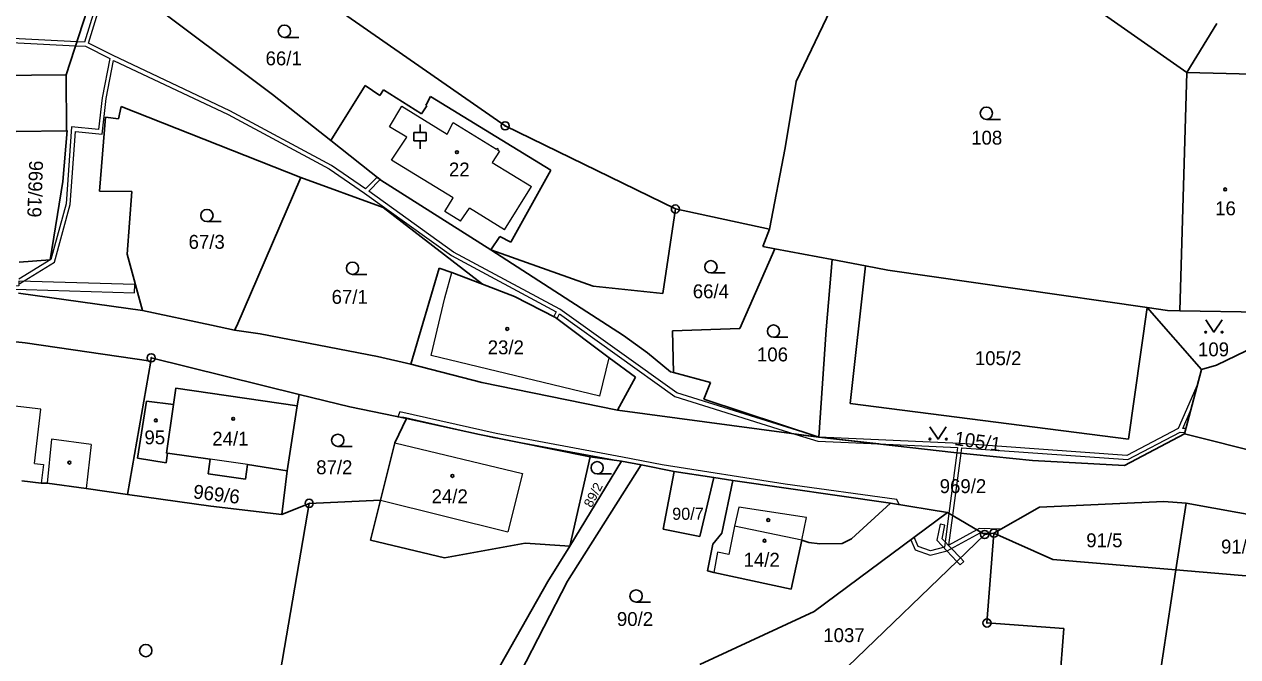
# Model space of a CAD drawing. Extents: x -754970 to -752637, y -970569 to -968179.
# Drawn here: x -753121.7 to -752973.4, y -969459.8 to -969382.5 of the extents above; entities that cross this region are included whole.
import ezdxf
from ezdxf.enums import TextEntityAlignment as Align

# ---------------------------------------------------------------- set-up
doc = ezdxf.new("R2010")
doc.units = 0
doc.header["$LTSCALE"] = 0.68
for name, color, linetype, lineweight in [('1', 7, 'Continuous', 25), ('13', 7, 'Continuous', 13), ('3', 7, 'Continuous', 25), ('4', 7, 'Continuous', 13), ('5', 7, 'Continuous', 25), ('8', 7, 'Continuous', 25)]:
    doc.layers.add(name, color=color, linetype=linetype, lineweight=lineweight)
doc.layers.add('2', color=7, linetype='Continuous')

msp = doc.modelspace()

# ---------------------------------------------------------------- linework, layer by layer
at = {"layer": '1'}
for p, q in [((-753014.52, -969363.86), (-752979.63, -969388.38)), ((-753112.53, -969376.1), (-753116.59, -969388.67)), ((-753091.37, -969391.06), (-753107.35, -969379.07)), ((-753062.94, -969394.9), (-753083.63, -969380.5)), ((-753027.39, -969389.48), (-753022.73, -969379.76)), ((-752975.98, -969382.36), (-752979.63, -969388.38)), ((-752979.63, -969388.38), (-752980.48, -969417.53)), ((-752979.63, -969388.38), (-752969.62, -969388.61)), ((-753125.25, -969388.72), (-753116.59, -969388.67)), ((-753116.56, -969395.51), (-753116.59, -969388.67)), ((-753080.04, -969389.98), (-753084.24, -969396.7)), ((-753080.04, -969389.98), (-753078.27, -969391.19)), ((-753028.7, -969397.57), (-753027.39, -969389.48)), ((-753084.24, -969396.7), (-753091.37, -969391.06)), ((-753077.82, -969390.49), (-753078.27, -969391.19)), ((-753073.17, -969393.44), (-753077.82, -969390.49)), ((-753072.07, -969391.32), (-753072.55, -969392.23)), ((-753072.07, -969391.32), (-753057.36, -969400.33)), ((-753109.88, -969392.51), (-753110.18, -969394.03)), ((-753087.91, -969401.22), (-753109.88, -969392.51)), ((-753072.53, -969392.44), (-753073.17, -969393.44)), ((-753072.55, -969392.23), (-753072.65, -969392.37)), ((-753072.65, -969392.37), (-753072.53, -969392.44)), ((-753111.78, -969393.82), (-753112.5, -969402.88)), ((-753110.18, -969394.03), (-753111.78, -969393.82)), ((-753122.72, -969395.58), (-753116.56, -969395.51)), ((-753116.99, -969401.72), (-753116.45, -969395.48)), ((-753116.56, -969395.51), (-753116.45, -969395.48)), ((-753042.13, -969405.06), (-753062.94, -969394.9)), ((-753078.12, -969401.54), (-753084.24, -969396.7)), ((-753030.65, -969407.55), (-753028.7, -969397.57)), ((-753057.36, -969400.33), (-753062.23, -969409.14)), ((-753118.56, -969411.3), (-753116.99, -969401.72)), ((-753087.91, -969401.22), (-753095.74, -969419.37)), ((-753087.91, -969401.22), (-753077.86, -969404.87)), ((-753064.69, -969410.06), (-753078.12, -969401.54)), ((-753112.5, -969402.88), (-753108.56, -969402.93)), ((-753108.56, -969402.93), (-753109.13, -969410.6)), ((-753077.86, -969404.87), (-753065.7, -969414.26)), ((-753043.66, -969415.4), (-753042.13, -969405.06)), ((-753030.65, -969407.55), (-753042.13, -969405.06)), ((-753031.44, -969409.65), (-753030.65, -969407.55)), ((-753063.6, -969408.43), (-753064.69, -969410.06)), ((-753062.23, -969409.14), (-753063.6, -969408.43)), ((-753109.13, -969410.6), (-753107.27, -969417.5)), ((-753064.69, -969410.06), (-753048.46, -969420.54)), ((-753064.69, -969410.06), (-753052.19, -969414.49)), ((-753029.99, -969409.93), (-753034.24, -969419.67)), ((-753029.99, -969409.93), (-753031.44, -969409.65)), ((-753022.98, -969411.26), (-753029.99, -969409.93)), ((-753118.56, -969411.3), (-753122.34, -969411.56)), ((-753071.02, -969412.3), (-753074.46, -969424.04)), ((-753069.44, -969412.82), (-753071.02, -969412.3)), ((-753023.69, -969419.83), (-753022.98, -969411.26)), ((-753022.98, -969411.26), (-753018.9, -969412.03)), ((-753018.9, -969412.03), (-753020.77, -969428.86)), ((-753018.9, -969412.03), (-753016.16, -969412.55)), ((-753065.7, -969414.26), (-753069.44, -969412.82)), ((-753016.16, -969412.55), (-752984.46, -969417.12)), ((-753065.7, -969414.26), (-753061.79, -969415.76)), ((-753052.19, -969414.49), (-753043.66, -969415.4)), ((-753107.27, -969417.5), (-753122.41, -969415.37)), ((-753056.77, -969418.32), (-753061.79, -969415.76)), ((-752975.99, -969424.16), (-752959, -969415.96)), ((-753107.27, -969417.5), (-753098.82, -969419.27)), ((-752986.78, -969433.23), (-752984.46, -969417.12)), ((-752984.46, -969417.12), (-752977.83, -969424.68)), ((-752984.46, -969417.12), (-752982, -969417.47)), ((-752982, -969417.47), (-752980.48, -969417.53)), ((-752980.48, -969417.53), (-752970.51, -969417.7)), ((-753098.82, -969419.27), (-753096.01, -969419.89)), ((-753095.74, -969419.37), (-753096.01, -969419.89)), ((-753050.24, -969423.29), (-753056.77, -969418.32)), ((-753042.5, -969419.97), (-753034.24, -969419.67)), ((-753121.61, -969421.42), (-753127.82, -969420.82)), ((-753092.88, -969420.35), (-753096.01, -969419.89)), ((-753078.54, -969423.09), (-753092.88, -969420.35)), ((-753048.46, -969420.54), (-753045.56, -969422.64)), ((-753042.36, -969425.08), (-753042.5, -969419.97)), ((-753024.62, -969432.98), (-753023.69, -969419.83)), ((-753106.24, -969423.68), (-753121.61, -969421.42)), ((-753045.56, -969422.64), (-753042.75, -969424.98)), ((-753109.09, -969439.97), (-753106.24, -969423.68)), ((-753106.2, -969423.27), (-753106.24, -969423.68)), ((-753106.2, -969423.27), (-753088.13, -969427.74)), ((-753074.46, -969424.04), (-753078.54, -969423.09)), ((-753074.46, -969424.04), (-753065.79, -969426.3)), ((-753047.03, -969425.62), (-753050.24, -969423.29)), ((-752977.83, -969424.68), (-752975.99, -969424.16)), ((-753047.03, -969425.62), (-753049.22, -969429.69)), ((-753042.75, -969424.98), (-753042.36, -969425.08)), ((-753042.36, -969425.08), (-753037.85, -969426.28)), ((-752979.9, -969432.57), (-752977.83, -969424.68)), ((-753065.79, -969426.3), (-753049.22, -969429.69)), ((-753038.66, -969428.33), (-753037.85, -969426.28)), ((-753107.88, -969435.56), (-753106.79, -969428.57)), ((-753106.79, -969428.57), (-753103.49, -969428.96)), ((-753088.35, -969429.15), (-753088.13, -969427.74)), ((-753088.13, -969427.74), (-753081.93, -969429.27)), ((-753024.62, -969432.98), (-753038.66, -969428.33)), ((-753103.49, -969428.96), (-753104.33, -969434.93)), ((-753088.35, -969429.15), (-753089.6, -969437.1)), ((-753074.99, -969430.69), (-753081.93, -969429.27)), ((-753049.22, -969429.69), (-753024.62, -969432.98)), ((-752986.78, -969433.23), (-753020.77, -969428.86)), ((-753074.99, -969430.69), (-753076.43, -969433.67)), ((-753066.07, -969432.66), (-753074.99, -969430.69)), ((-753066.07, -969432.66), (-753052.54, -969435.38)), ((-753008.12, -969434.83), (-753024.62, -969432.98)), ((-752979.9, -969432.57), (-752987.24, -969436.42)), ((-752965.87, -969436.11), (-752979.9, -969432.57)), ((-753078.17, -969440.69), (-753076.43, -969433.67)), ((-753104.37, -969436.12), (-753107.88, -969435.56)), ((-753104.19, -969434.95), (-753104.37, -969436.12)), ((-753104.33, -969434.93), (-753104.19, -969434.95)), ((-753104.19, -969434.95), (-753098.98, -969435.68)), ((-753098.98, -969435.68), (-753099.23, -969437.46)), ((-753052.54, -969435.38), (-753055.02, -969446.29)), ((-753048.74, -969435.91), (-753055.02, -969446.29)), ((-753052.54, -969435.38), (-753048.74, -969435.91)), ((-753046.31, -969436.35), (-753048.74, -969435.91)), ((-752998.49, -969435.81), (-753008.12, -969434.83)), ((-752987.24, -969436.42), (-752998.49, -969435.81)), ((-753099.23, -969437.46), (-753094.68, -969438.11)), ((-753094.68, -969438.11), (-753094.43, -969436.32)), ((-753089.6, -969437.1), (-753094.43, -969436.32)), ((-753090.24, -969442.45), (-753089.6, -969437.1)), ((-753055.32, -969450.6), (-753046.31, -969436.35)), ((-753046.31, -969436.35), (-753042.27, -969437.18)), ((-753043.63, -969444.23), (-753042.27, -969437.18)), ((-753037.42, -969437.89), (-753042.27, -969437.18)), ((-753122.01, -969438.33), (-753119.63, -969438.61)), ((-753119.63, -969438.61), (-753118.92, -969438.59)), ((-753118.92, -969438.59), (-753114.14, -969439.25)), ((-753037.42, -969437.89), (-753039.14, -969445.14)), ((-753035.13, -969438.29), (-753037.42, -969437.89)), ((-753035.13, -969438.29), (-753036.47, -969444.72)), ((-753015.83, -969441.05), (-753035.13, -969438.29)), ((-753109.09, -969439.97), (-753114.14, -969439.25)), ((-753098.92, -969441.41), (-753109.09, -969439.97)), ((-753090.24, -969442.45), (-753098.92, -969441.41)), ((-753086.89, -969441.07), (-753095.11, -969489.22)), ((-753086.89, -969441.07), (-753090.24, -969442.45)), ((-753078.17, -969440.69), (-753086.89, -969441.07)), ((-753078.17, -969440.69), (-753079.38, -969445.56)), ((-753015.83, -969441.05), (-753020.61, -969445.42)), ((-753008.89, -969442.19), (-753015.83, -969441.05)), ((-753003.21, -969444.72), (-752997.63, -969441.54)), ((-752997.63, -969441.54), (-752982.45, -969440.86)), ((-752982.45, -969440.86), (-752979.72, -969441.05)), ((-752980.96, -969449.2), (-752979.72, -969441.05)), ((-752979.72, -969441.05), (-752957.16, -969445.1)), ((-753008.89, -969442.19), (-753025.16, -969454.29)), ((-753008.89, -969442.19), (-753004.33, -969444.88)), ((-753039.14, -969445.14), (-753043.63, -969444.23)), ((-753036.47, -969444.72), (-753037.56, -969446.06)), ((-753029.33, -969468.96), (-753004.33, -969444.88)), ((-753004.33, -969444.88), (-753003.21, -969444.72)), ((-753003.21, -969444.72), (-753004.06, -969455.7)), ((-753003.21, -969444.72), (-752996, -969447.92)), ((-753079.38, -969445.56), (-753070.36, -969447.75)), ((-753070.36, -969447.75), (-753060.51, -969445.95)), ((-753055.02, -969446.29), (-753060.51, -969445.95)), ((-753057.73, -969450.62), (-753055.02, -969446.29)), ((-753037.56, -969446.06), (-753038.21, -969449.31)), ((-753027.97, -969451.57), (-753026.7, -969445.59)), ((-753025.83, -969445.86), (-753026.7, -969445.59)), ((-753024.49, -969446), (-753025.83, -969445.86)), ((-753021.74, -969445.97), (-753024.49, -969446)), ((-753020.61, -969445.42), (-753021.74, -969445.97)), ((-753038.21, -969449.31), (-753037.45, -969449.51)), ((-752996, -969447.92), (-752980.96, -969449.2)), ((-752988.75, -969500.54), (-752980.96, -969449.2)), ((-752980.96, -969449.2), (-752969.96, -969450.14)), ((-753057.73, -969450.62), (-753079.26, -969488.65)), ((-753061.11, -969461.85), (-753055.32, -969450.6)), ((-753027.97, -969451.57), (-753037.45, -969449.51)), ((-753025.16, -969454.29), (-753039.13, -969460.76)), ((-753004.06, -969455.7), (-752994.68, -969456.37)), ((-752994.68, -969456.37), (-752996.05, -969475.33))]:
    msp.add_line(p, q, dxfattribs=at)
msp.add_lwpolyline([(-753103.49, -969428.96), (-753103.19, -969426.99), (-753088.35, -969429.15)], dxfattribs=at)
at = {"layer": '13'}
for points in [[(-753112.08, -969377.25), (-753114.34, -969384.65), (-753115.28, -969384.61), (-753144.3, -969383.11)], [(-753122.27, -969414.17), (-753118.02, -969411.58), (-753116.1, -969404.5), (-753115.46, -969395.58), (-753112.19, -969395.9), (-753111.72, -969391.54), (-753110.79, -969386.89), (-753096.81, -969393.52), (-753084.43, -969400.16), (-753080.12, -969403.13), (-753069.51, -969410.76), (-753056.72, -969417.63), (-753056.99, -969418.21), (-753056.77, -969418.32), (-753056.57, -969418.47), (-753056.29, -969417.9), (-753042.19, -969428), (-753027.52, -969432.59), (-753024.62, -969432.98), (-753041.97, -969427.54), (-753056.26, -969417.31), (-753069.24, -969410.33), (-753079.59, -969402.89), (-753078.21, -969401.47), (-753078.6, -969401.16), (-753080.01, -969402.6), (-753084.17, -969399.74), (-753096.58, -969393.07), (-753110.86, -969386.3), (-753113.86, -969384.78), (-753111.61, -969377.45)], [(-753144.41, -969383.61), (-753115.44, -969385.1), (-753114.22, -969385.16), (-753111.25, -969386.66), (-753112.21, -969391.46), (-753112.63, -969395.36), (-753115.92, -969395.03), (-753116.6, -969404.42), (-753118.45, -969411.26), (-753122.38, -969413.65)]]:
    msp.add_lwpolyline(points, dxfattribs=at)
for points in [[(-753108.21, -969414.32), (-753122.38, -969413.88), (-753122.39, -969414.45), (-753128.59, -969414.54), (-753129.47, -969414.66), (-753108.24, -969415.32)], [(-752978.26, -969426.31), (-752980.68, -969431.93), (-752986.95, -969435.21), (-753007.34, -969433.75), (-753024.62, -969432.98), (-753017.27, -969433.8), (-753007.64, -969434.23), (-753007.73, -969434.87), (-753007.23, -969434.92), (-753007.14, -969434.26), (-752986.84, -969435.71), (-752980.43, -969432.37), (-752979.86, -969432.42), (-752979.73, -969431.93), (-752980.12, -969431.9), (-752979.11, -969429.56)], [(-753076.04, -969430.47), (-753075.54, -969430.58), (-753075.5, -969430.47), (-753064.37, -969433), (-753063.87, -969433.1), (-753048.74, -969435.91), (-753046.31, -969436.35), (-753042.27, -969437.18), (-753037.42, -969437.89), (-753035.13, -969438.29), (-753015.83, -969441.05), (-753015.37, -969441.13), (-753014.77, -969441.22), (-753015.06, -969440.6), (-753028.71, -969438.74), (-753043.74, -969436.36), (-753048.61, -969435.42), (-753064.05, -969432.54), (-753075.8, -969429.89)], [(-753027.52, -969432.59), (-753024.71, -969433.47), (-753017.27, -969433.8), (-753024.62, -969432.98)], [(-753007.73, -969434.87), (-753008.71, -969442.3), (-753008.24, -969442.57), (-753007.23, -969434.92)], [(-753008.71, -969442.3), (-753009.26, -969446.43), (-753010.95, -969446.87), (-753012.45, -969446.34), (-753012.96, -969445.22), (-753013.37, -969445.52), (-753012.82, -969446.74), (-753010.98, -969447.39), (-753008.94, -969446.87), (-753004.9, -969444.66), (-753004.7, -969444.66), (-753005.3, -969444.31), (-753008.72, -969446.18), (-753008.24, -969442.57)], [(-753007.74, -969448.16), (-753007.3, -969447.74), (-753009.52, -969445.4), (-753009.2, -969443.72), (-753009.79, -969443.61), (-753010.17, -969445.59)], [(-753005.02, -969444.15), (-753005.3, -969444.31), (-753004.7, -969444.66), (-753003.21, -969444.72), (-753002.37, -969444.24)], [(-753007.74, -969448.16), (-753007.33, -969448.6), (-753006.89, -969448.18), (-753007.3, -969447.74)]]:
    msp.add_lwpolyline(points, close=True, dxfattribs=at)
at = {"layer": '3'}
for p, q in [((-753089.923, -969384.08), (-753088.173, -969384.08)), ((-753004.133, -969394.11), (-753002.383, -969394.11)), ((-753074.091, -969395.721), (-753072.589, -969395.721)), ((-753074.091, -969396.722), (-753074.091, -969395.721)), ((-753073.34, -969395.721), (-753073.34, -969394.72)), ((-753072.589, -969396.722), (-753072.589, -969395.721)), ((-753074.091, -969396.722), (-753072.589, -969396.722)), ((-753073.34, -969397.72), (-753073.34, -969396.722)), ((-753099.383, -969406.61), (-753097.633, -969406.61)), ((-753081.593, -969413.07), (-753079.843, -969413.07)), ((-753037.793, -969412.88), (-753036.043, -969412.88)), ((-753030.143, -969420.75), (-753028.393, -969420.75)), ((-753083.393, -969434.11), (-753081.643, -969434.11)), ((-753051.693, -969437.46), (-753049.943, -969437.46)), ((-753046.933, -969453.15), (-753045.183, -969453.15))]:
    msp.add_line(p, q, dxfattribs=at)
for points in [[(-752977.32, -969418.629), (-752976.32, -969420.13), (-752975.32, -969418.629)], [(-753011.03, -969431.709), (-753010.03, -969433.21), (-753009.03, -969431.709)]]:
    msp.add_lwpolyline(points, dxfattribs=at)
for centre, radius in [((-753089.9229, -969383.3298), 0.75), ((-753004.1329, -969393.3598), 0.75), ((-753099.3829, -969405.8598), 0.75), ((-753081.5929, -969412.3198), 0.75), ((-753037.7929, -969412.1298), 0.75), ((-753030.1429, -969419.9998), 0.75), ((-752977.32, -969420.1295), 0.1), ((-752975.32, -969420.1295), 0.1), ((-753083.3929, -969433.3598), 0.75), ((-753011.03, -969433.2095), 0.1), ((-753009.03, -969433.2095), 0.1), ((-753051.6929, -969436.7098), 0.75), ((-753046.9329, -969452.3998), 0.75), ((-753106.8629, -969459.0798), 0.75)]:
    msp.add_circle(centre, radius, dxfattribs=at)
at = {"layer": '4'}
for p, q in [((-753077.08, -969395), (-753075.55, -969392.5)), ((-753075.55, -969392.5), (-753070.03, -969395.93)), ((-753070.03, -969395.93), (-753069.29, -969394.49)), ((-753069.29, -969394.49), (-753064.01, -969397.75)), ((-753074.95, -969396.3), (-753077.08, -969395)), ((-753076.81, -969399.11), (-753074.95, -969396.3)), ((-753063.64, -969397.98), (-753064.52, -969399.37)), ((-753064.01, -969397.75), (-753063.95, -969397.62)), ((-753063.95, -969397.62), (-753063.81, -969397.72)), ((-753063.81, -969397.72), (-753063.87, -969397.84)), ((-753063.87, -969397.84), (-753063.64, -969397.98)), ((-753069.31, -969403.72), (-753076.81, -969399.11)), ((-753064.52, -969399.37), (-753059.73, -969402.32)), ((-753063, -969407.6), (-753059.73, -969402.32)), ((-753070.33, -969405.37), (-753069.31, -969403.72)), ((-753068.4, -969406.57), (-753070.33, -969405.37)), ((-753068.4, -969406.57), (-753067.31, -969404.95)), ((-753063, -969407.6), (-753067.31, -969404.95)), ((-753070.3, -969415.93), (-753069.44, -969412.82)), ((-753071.97, -969422.99), (-753070.3, -969415.93)), ((-753051.37, -969427.95), (-753071.97, -969422.99)), ((-753051.37, -969427.95), (-753050.24, -969423.29)), ((-753118.4, -969433.23), (-753118.92, -969438.59)), ((-753113.55, -969433.86), (-753118.4, -969433.23)), ((-753113.55, -969433.86), (-753114.14, -969439.25)), ((-753076.43, -969433.67), (-753060.84, -969437.43)), ((-753094.43, -969436.32), (-753098.98, -969435.68)), ((-753120.48, -969436.2), (-753119.38, -969436.33)), ((-753119.38, -969436.33), (-753119.63, -969438.61)), ((-753060.84, -969437.43), (-753062.6, -969444.54)), ((-753078.17, -969440.69), (-753062.6, -969444.54)), ((-753034.38, -969441.52), (-753034.9, -969443.86)), ((-753026.1, -969442.79), (-753034.38, -969441.52)), ((-753026.7, -969445.59), (-753026.1, -969442.79)), ((-753026.7, -969445.59), (-753034.9, -969443.86))]:
    msp.add_line(p, q, dxfattribs=at)
for points in [[(-753120.48, -969436.2), (-753119.67, -969429.55), (-753129.49, -969428.41)], [(-753034.9, -969443.86), (-753035.61, -969447.32), (-753037, -969447.05), (-753037.45, -969449.51)]]:
    msp.add_lwpolyline(points, dxfattribs=at)
at = {"layer": '5'}
for centre in [(-753068.8268, -969398.1192), (-752974.9468, -969402.6692), (-753062.6768, -969419.7392), (-753105.6268, -969430.9192), (-753096.1768, -969430.7292), (-753116.1968, -969436.0892), (-753069.3868, -969437.7192), (-753030.7868, -969443.1092), (-753031.2368, -969445.6392)]:
    msp.add_circle(centre, 0.175, dxfattribs=at)
at = {"layer": '8'}
for centre, radius in [((-753062.94, -969394.8999), 0.5), ((-753062.94, -969394.8999), 0.0303), ((-753042.13, -969405.0599), 0.5), ((-753042.13, -969405.0599), 0.0303), ((-753106.2, -969423.2699), 0.5), ((-753106.2, -969423.2699), 0.0303), ((-753086.89, -969441.0699), 0.5), ((-753086.89, -969441.0699), 0.0303), ((-753004.33, -969444.8799), 0.5), ((-753004.33, -969444.8799), 0.0303), ((-753003.21, -969444.7199), 0.5), ((-753003.21, -969444.7199), 0.0303), ((-753004.06, -969455.6999), 0.5), ((-753004.06, -969455.6999), 0.0303)]:
    msp.add_circle(centre, radius, dxfattribs=at)

# ---------------------------------------------------------------- texts
at = {"layer": '2'}
for s, height, p in [('66/1', 1.7, (-753090.009, -969387.495)), ('108', 1.7, (-753004.089, -969397.195)), ('22', 1.7, (-753068.549, -969401.085)), ('16', 1.7, (-752974.909, -969405.835)), ('67/3', 1.7, (-753099.419, -969409.935)), ('67/1', 1.7, (-753081.939, -969416.665)), ('66/4', 1.7, (-753037.799, -969415.985)), ('23/2', 1.7, (-753062.859, -969422.835)), ('106', 1.7, (-753030.269, -969423.705)), ('105/2', 1.7, (-753002.69, -969424.165)), ('109', 1.7, (-752976.369, -969423.085)), ('95', 1.7, (-753105.759, -969433.845)), ('24/1', 1.7, (-753096.519, -969434.005)), ('87/2', 1.7, (-753083.819, -969437.505)), ('969/2', 1.7, (-753006.99, -969439.815)), ('24/2', 1.7, (-753069.719, -969441.055)), ('90/7', 1.479, (-753040.6, -969443.079)), ('91/5', 1.7, (-752989.709, -969446.435)), ('91/6', 1.7, (-752973.239, -969447.205)), ('14/2', 1.7, (-753031.589, -969448.815)), ('90/2', 1.7, (-753047.069, -969456.065)), ('1037', 1.7, (-753021.53, -969458.045))]:
    msp.add_text(s, height=height, dxfattribs=at).set_placement(p, align=Align.CENTER)
for s, rotation, p in [('969/19', 268, (-753121.2245, -969402.5893)), ('105/1', 352, (-753005.2983, -969434.3192)), ('969/6', 353, (-753098.3081, -969440.7881))]:
    msp.add_text(s, height=1.7, rotation=rotation, dxfattribs=at).set_placement(p, align=Align.CENTER)
at = {"layer": '2', "width": 1.05}
msp.add_text('89/2', height=1.14, rotation=63, dxfattribs=at).set_placement((-753051.6683, -969440.2873), align=Align.CENTER)

doc.saveas('drawing.dxf')
